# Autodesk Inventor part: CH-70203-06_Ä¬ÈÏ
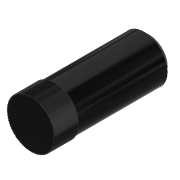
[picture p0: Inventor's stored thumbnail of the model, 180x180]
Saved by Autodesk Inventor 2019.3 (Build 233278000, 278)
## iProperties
Created: 2010-06
Part Number: CH-70203-06_Ä¬ÈÏ
Material: Ogólny
Document SubType Name: Modeling
Designer: CADENGINEERING4
Density: 1 g/cm^3
Appearance: Gładki — czarny
Author: CADENGINEERING4
Revision Number: ÈÎºÎ
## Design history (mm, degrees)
feature "NONE"
node "Bryła1"
